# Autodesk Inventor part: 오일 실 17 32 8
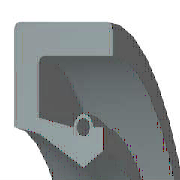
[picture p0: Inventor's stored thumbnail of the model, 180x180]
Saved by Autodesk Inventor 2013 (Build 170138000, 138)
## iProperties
IsCustomPart: 1
Created: 2012-02
Part Number: 오일 실 17 32 8
Material: 고무
Description: 오일-실
Document SubType Name: Modeling
Standard: KS B 2804
Designer: test
Standards Organization: KS
Language: ko-KR
Size Designation: S - 17 32 8
Categories: <MemberInstance><Categories><Category DisplayName="샤프트 부품" InternalName="7f7aeb1f-a693-4053-b835-cee3144e0d98" Mnemonic="SHFT"><Category DisplayName="실링" Intern
Density: 0.93 g/cm^3
Mass: 1.89534 g
Surface Area: 30.829 cm^2
Volume: 2.038 cm^3
Author: test
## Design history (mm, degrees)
revolve "본체" stored, may be unused: angle "d17" = 90 deg
revolve "스프링1" stored, may be unused: angle "d18" = 90 deg
body "Solid1"
sketch "스케치1"
  geometry: L1 (0, 16)-(8, 16); L2 (8, 16)-(8, 14.75); L3 (8, 14.75)-(1.75, 14.75); L4 (0, 16)-(0, 10.6); L5 (0, 10.6)-(1.75, 10.25); L6 (1.75, 10.25)-(4.9, 8.5); L7 (4.9, 8.5)-(0, 8.5); L8 (6.3, 9.375)-(6.3, 10.6); L9 (0, 0)-(9.586, 0) reference; L10 (4.9, 8.5)-(6.3, 9.375); L11 (0, 18)-(0, -3) reference; L12 (-1.917, 0)-(11.503, 0) reference; L13 (4.2, 10.6)-(1.75, 11.09); L14 (1.75, 11.09)-(1.75, 14.75); L15 (6.3, 10.6)-(5.6, 10.6); C1 r 0.455 at (4.9, 10.6); A1 r 0.7 centre (4.9, 10.6) between (5.6, 10.6) and (4.2, 10.6)
  constraints: 26 end point, 5 horizontal alignment, 4 perpendicular, 2 centre point, 2 collinear, 2 horizontal, 2 parallel, 2 point on circle, 2 point on line, 2 vertical alignment, 1 coincident
  dimensions: "d0" = 32 diameter of L1 L9 (= SD2); "d1" = 18.75 diameter of L8.start L9 (= ABDM); "d2" = 1.25 distance of L1.end L2.end (computed from SD); "d3" = 0.91 diameter of C1 (= SPDI); "d4" = 1.4 diameter of A1 (= SPDA); "d5" = 17 diameter of L6.end L9 (= NND); "d6" = 20.5 diameter of L5.end L9 (= TKDM); "d7" = 21.2 diameter of L4.end L9 (= HLDM); "d8" = 4.9 distance from line of C1.centre L4 (= SPDST); "d9" = 6.3 distance between parallel lines of L8 L4 (= SDI); "d10" = 8 distance between parallel lines of L2 L4 (= SWDT); "d12" = 1.75 distance between parallel lines of L14 L4 (= SD)
fillet "모깎기1" dims "d11" = 0.3 (= RR)
other parameters: "SD2" = 32 [user parameter; used in 1 equation term], "SWDT" = 8 [user parameter; used in 1 equation term], "RR" = 0.3 [user parameter; used in 1 equation term], "SD" = 1.75 [user parameter; used in 2 equation terms], "NND" = 17 [user parameter; used in 1 equation term], "SPDA" = 1.4 [user parameter; used in 1 equation term], "SPDI" = 0.91 [user parameter; used in 1 equation term], "TKDM" = 20.5 [user parameter; used in 1 equation term], "HLDM" = 21.2 [user parameter; used in 1 equation term], "ABDM" = 18.75 [user parameter; used in 1 equation term], "SDI" = 6.3 [user parameter; used in 1 equation term], "SPDST" = 4.9 [user parameter; used in 1 equation term], "d13" = 0, "d14" = 0, "d15" = 0, "LAB" = 0.35 [user parameter]
